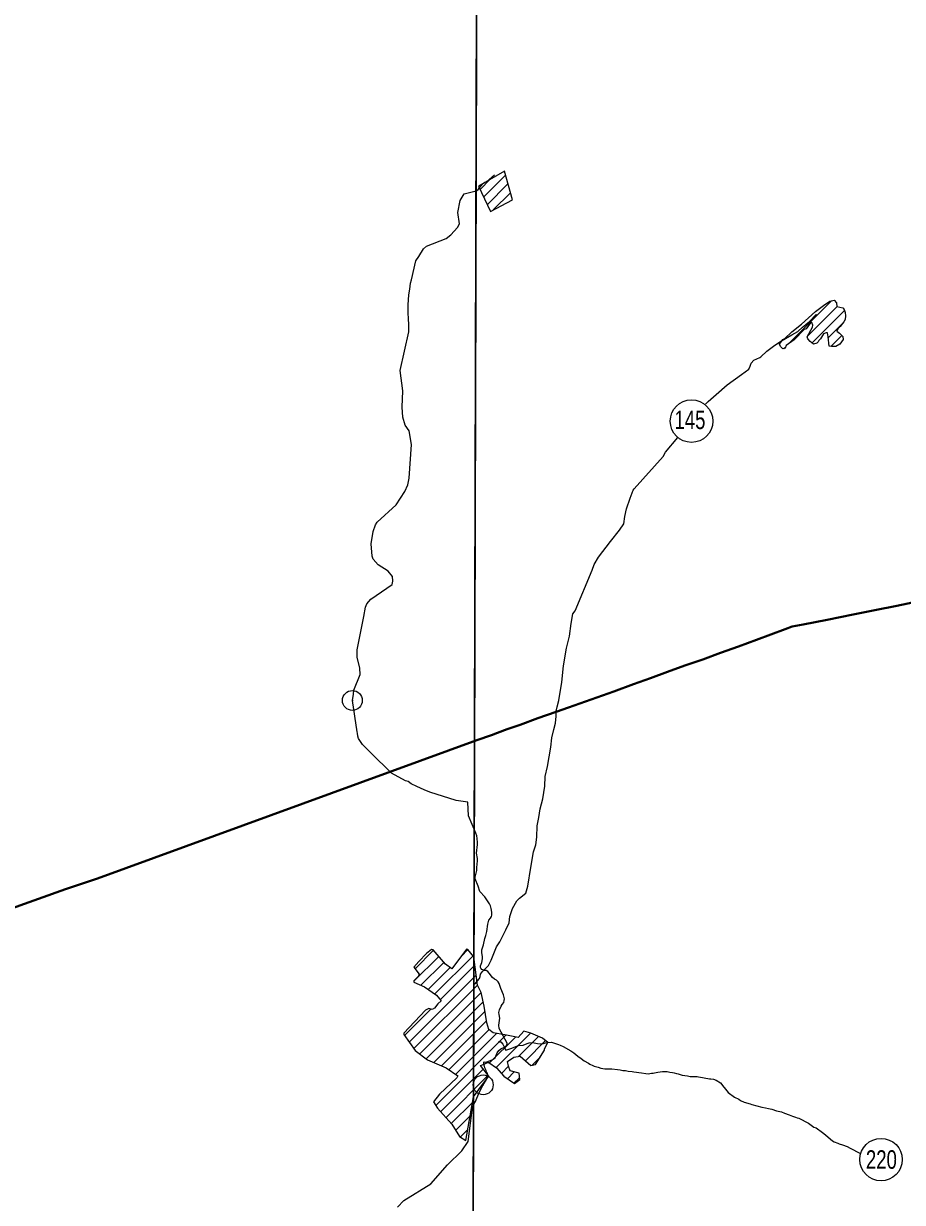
# Model space of a CAD drawing. Extents: x 553962 to 842807, y 8883888 to 9032388.
# Drawn here: x 583922 to 587242, y 8911869 to 8916321 of the extents above; entities that cross this region are included whole.
import ezdxf
from ezdxf.enums import TextEntityAlignment as Align

# ---------------------------------------------------------------- set-up
doc = ezdxf.new("R2010")
doc.units = 0
doc.header["$LTSCALE"] = 150
doc.header["$PDMODE"] = 32
doc.header["$PDSIZE"] = 75
doc.layers.add('6', color=7, linetype='Continuous', lineweight=13)

msp = doc.modelspace()

# ---------------------------------------------------------------- linework, layer by layer
at = {"layer": '6'}
for p, q in [((585646.2, 8915694.7), (585684.3, 8915732.9)), ((585659.8, 8915665.9), (585742.7, 8915748.8)), ((585654.5, 8915713.5), (585659, 8915718.1)), ((585673.4, 8915637.1), (585751.8, 8915715.5)), ((585696.2, 8915617.4), (585761, 8915682.2)), ((586813.8, 8915113.8), (586974.3, 8915274.2)), ((586882.8, 8915140.3), (586994.4, 8915251.9)), ((586900.1, 8915115.2), (587023, 8915238.1)), ((586961.6, 8915134.2), (587014.3, 8915187)), ((586972, 8915102.2), (587012.5, 8915142.8)), ((586794.2, 8915094.1), (586800.9, 8915100.8)), ((585164.2, 8913764.7), (585168, 8913788.9)), ((585396.8, 8912704.8), (585490.4, 8912798.3)), ((585400.9, 8912751.3), (585470.7, 8912821)), ((585475.4, 8912656.1), (585619.8, 8912800.4)), ((585574.5, 8912797.6), (585600.5, 8912823.6)), ((585423.2, 8912688.8), (585510.1, 8912775.6)), ((585450.2, 8912673.2), (585533, 8912756.1)), ((585495.7, 8912633.9), (585626.7, 8912764.9)), ((585378.8, 8912474.6), (585631.4, 8912727.2)), ((585396.4, 8912449.8), (585636.2, 8912689.5)), ((585418.5, 8912429.5), (585650.2, 8912661.2)), ((585442.6, 8912411.1), (585658.2, 8912626.7)), ((585361.2, 8912499.4), (585461.2, 8912599.4)), ((585471.2, 8912397.3), (585665.1, 8912591.2)), ((585501.1, 8912384.8), (585671, 8912554.7)), ((585528.9, 8912370.1), (585680.2, 8912521.4)), ((585478.8, 8912235.2), (585744.3, 8912500.7)), ((585553.8, 8912352.6), (585708.5, 8912507.3)), ((585682.1, 8912396.1), (585779.6, 8912493.6)), ((585706.9, 8912378.4), (585836.5, 8912508)), ((585791.3, 8912420.4), (585866.7, 8912495.8)), ((585817.4, 8912404.1), (585893.6, 8912480.2)), ((585726.9, 8912356), (585754.2, 8912383.3)), ((585842.2, 8912386.5), (585874.3, 8912418.5)), ((585497.3, 8912211.3), (585658.6, 8912372.5)), ((585517.3, 8912188.8), (585677.4, 8912349)), ((585749.5, 8912336.2), (585775.3, 8912362)), ((585774.5, 8912318.7), (585795.5, 8912339.8)), ((585537.3, 8912166.4), (585618.5, 8912247.6)), ((585554.2, 8912140.9), (585609.2, 8912195.9)), ((585572, 8912116.2), (585600, 8912144.3))]:
    msp.add_line(p, q, dxfattribs=at)
for points in [[(585656.3, 8924738.8), (585614.8, 8909969.8), (585573.6, 8896026.7)], [(585659.6, 8915718.8), (585664, 8915721.8), (585674.1, 8915726.3), (585679.1, 8915730.6), (585692.1, 8915742.6), (585701, 8915749.9)], [(585414.9, 8915441.5), (585432.8, 8915470.1), (585444.4, 8915480.8), (585518.2, 8915510), (585536, 8915523.2), (585560.6, 8915550.4), (585569.1, 8915565.3), (585561.9, 8915607.2), (585571.5, 8915653.5), (585585.9, 8915678), (585631.7, 8915689.4), (585634.6, 8915690.8), (585639.6, 8915694.9), (585655.2, 8915714.2)], [(585387.2, 8915353.3), (585404.3, 8915424.6), (585414.9, 8915441.5)], [(585376.5, 8915206.1), (585374.8, 8915228.7), (585374.3, 8915258.9), (585377.8, 8915297.1), (585380.9, 8915318.6), (585384.2, 8915340.2), (585387.2, 8915353.3)], [(585344.3, 8915010.4), (585377.6, 8915157), (585377.3, 8915185), (585376.5, 8915206.1)], [(585258.2, 8914437.7), (585330, 8914503.1), (585362.7, 8914553.7), (585373.3, 8914579.2), (585378.8, 8914604.6), (585387.7, 8914732), (585378.4, 8914783.1), (585363.1, 8914804.4), (585355, 8914834.1), (585351.6, 8914872.3), (585354.6, 8914933.5), (585344.3, 8915010.4)], [(585317.3, 8914216), (585316.1, 8914232.9), (585298.9, 8914252.4), (585262, 8914276.7), (585242.9, 8914298.7), (585238.3, 8914309.6), (585235.2, 8914355.7), (585242.8, 8914403.2), (585251.4, 8914427.6), (585258.2, 8914437.7)], [(585206.8, 8914082.2), (585213.6, 8914117), (585218.3, 8914129.3), (585233.9, 8914146.7), (585314.4, 8914203.2), (585317.3, 8914215.7), (585317.3, 8914216)], [(585168, 8913788.9), (585170.2, 8913803.4), (585194, 8913862.9), (585192.3, 8913886.6), (585182.1, 8913928.2), (585182.1, 8913956.3), (585206.8, 8914082.2)], [(585202.5, 8913598.6), (585187.4, 8913621.3), (585184.9, 8913630.1), (585183, 8913640.7), (585182.1, 8913645.8), (585164.2, 8913764.7)], [(585365.1, 8913461), (585312.1, 8913489.8), (585233.9, 8913567.4), (585202.5, 8913598.6)], [(585556.7, 8913386.5), (585456.6, 8913418.5), (585434.8, 8913426.6), (585408.2, 8913439.8), (585386, 8913450.3), (585374.6, 8913458.3), (585365.1, 8913461)], [(585630.2, 8913263.8), (585602.7, 8913329.2), (585600.5, 8913381), (585556.7, 8913386.5)], [(585736.2, 8912623.7), (585737.8, 8912631.2), (585738.3, 8912638), (585735.4, 8912652.4), (585724.9, 8912676.3), (585718.3, 8912696.1), (585715, 8912702.5), (585708.5, 8912708.9), (585700.5, 8912712.7), (585693.4, 8912718.1), (585681, 8912734.9), (585675.2, 8912740.7), (585669.2, 8912744.5), (585662.6, 8912744.7), (585653.1, 8912748.3), (585649.1, 8912753.1), (585647.6, 8912756.5), (585647.8, 8912762.3), (585652.8, 8912775.5), (585655.5, 8912788.5), (585655.4, 8912796.9), (585652.9, 8912813.2), (585653.4, 8912822.4), (585659.4, 8912841.6), (585663.8, 8912865.3), (585667.9, 8912876.9), (585671.8, 8912892.1), (585676, 8912920.4), (585680, 8912935.4), (585685.6, 8912942.4), (585689.2, 8912948.4), (585690.5, 8912953.8), (585690.6, 8912965.7), (585688.4, 8912978.7), (585685.4, 8912989.5), (585682.3, 8912996.3), (585663.9, 8913022.7), (585646, 8913043.7), (585639.3, 8913063.9), (585628.3, 8913091.6), (585627.9, 8913097.2), (585633.8, 8913122.4), (585634.1, 8913133.2), (585636.9, 8913159.3), (585636.4, 8913167.7), (585632.5, 8913187.7), (585636.7, 8913220.8), (585636.8, 8913228.4), (585635.7, 8913243), (585633.6, 8913253.8), (585630.2, 8913263.8)], [(585622.7, 8912796.8), (585600.5, 8912823.7), (585595.2, 8912825), (585539.5, 8912751.2), (585515.6, 8912769.3), (585469.4, 8912822.4), (585462.9, 8912823.7), (585443.5, 8912809), (585414.9, 8912778.3), (585415.6, 8912779)], [(585622.1, 8912267.7), (585652.2, 8912309.6), (585680.1, 8912345.6), (585648.2, 8912385.5), (585662.2, 8912391.5), (585674.1, 8912397.5), (585680.1, 8912397.5), (585708.1, 8912377.6), (585736.1, 8912345.6), (585776.1, 8912317.6), (585796.1, 8912333.6), (585794.1, 8912357.6), (585760.1, 8912365.6), (585754.1, 8912383.5), (585750.1, 8912401.5), (585774.1, 8912417.5), (585798.1, 8912421.5), (585838, 8912385.5), (585856, 8912389.5), (585890, 8912443.5), (585890, 8912449.5), (585902, 8912473.5), (585882, 8912489.5), (585838, 8912507.5), (585812.1, 8912515.5), (585790.1, 8912491.5), (585740.1, 8912501.5), (585696.1, 8912509.5), (585680.1, 8912521.5), (585672.1, 8912547.5), (585662.2, 8912609.5), (585650.2, 8912661.4), (585636.2, 8912689.4), (585622.7, 8912796.8)], [(585415.6, 8912779), (585396.2, 8912757.3), (585416.2, 8912731.2), (585414.5, 8912723), (585396.8, 8912705.3), (585396.8, 8912701), (585436.1, 8912682.8), (585481.6, 8912651.8), (585498.9, 8912629.7), (585486.4, 8912619.5), (585473.8, 8912602.6), (585466, 8912598.1), (585452.6, 8912601.9), (585439.9, 8912594.7), (585358.3, 8912507.7), (585358.3, 8912503.4), (585401.6, 8912442.4), (585447.4, 8912407.4), (585518.3, 8912377.6), (585561.9, 8912346.9), (585558.9, 8912339.9), (585492.8, 8912277.7), (585470.1, 8912248.8), (585485.7, 8912224.4), (585539.5, 8912164), (585568.8, 8912118.3), (585592.6, 8912103), (585622.1, 8912267.7)], [(585658.3, 8912313), (585669.3, 8912330.1), (585674.8, 8912344.1), (585674.7, 8912356.1), (585670, 8912363.9), (585669.5, 8912366.5), (585664.5, 8912377.1), (585660.4, 8912393.1), (585660.6, 8912399.1), (585661.4, 8912399.7), (585667, 8912398.8), (585671.5, 8912399.6), (585691.6, 8912407.8), (585703.4, 8912415.2), (585710.9, 8912433.7), (585717.4, 8912443.1), (585724.5, 8912449.1), (585741.6, 8912456.2), (585745.8, 8912461.4), (585749, 8912467.6), (585749.3, 8912469.8), (585718.8, 8912525.6), (585717.8, 8912538.1), (585721, 8912565.3), (585718.2, 8912578.9), (585717.9, 8912586.7), (585719.7, 8912596.1), (585725.9, 8912610.6), (585729.7, 8912616.2), (585736.2, 8912623.7)], [(585335.1, 8911850.8), (585358.8, 8911875.8), (585459.9, 8911939.1), (585523.3, 8912010.5), (585577.2, 8912063.6), (585601.4, 8912098.4), (585618, 8912226.8), (585623.8, 8912242.6), (585628.7, 8912250.5), (585642.8, 8912284.1), (585658.3, 8912313)]]:
    msp.add_lwpolyline(points, dxfattribs=at)
for points in [[(585645.8, 8921027.3), (574684.9, 8921064.7), (574653.9, 8910009.3), (585614.8, 8909969.8)], [(585640, 8915707.7), (585685.4, 8915611.8), (585768.3, 8915655.4), (585738.6, 8915763.7)], [(586913.1, 8915233.4), (586943.5, 8915256), (586968, 8915272.7), (586983.7, 8915276.6), (586992.5, 8915266.8), (586993.5, 8915252.1), (587016, 8915247.2), (587021.9, 8915241.3), (587025.8, 8915229.5), (587026.8, 8915216.8), (587024.8, 8915203), (587019.9, 8915194.2), (587006.2, 8915176.6), (586997.4, 8915168.7), (586993.5, 8915159.9), (587003.3, 8915152), (587016, 8915139.3), (587018, 8915127.5), (587005.2, 8915109.9), (586989.5, 8915102), (586973.9, 8915102), (586965, 8915103), (586961.1, 8915138.3), (586958.2, 8915153), (586953.3, 8915153), (586943.5, 8915149.1), (586931.7, 8915130.5), (586925.8, 8915124.6), (586922.9, 8915119.7), (586918, 8915113.8), (586906.2, 8915110.8), (586892.5, 8915120.7), (586884.6, 8915130.5), (586881.7, 8915138.3), (586901.3, 8915174.6), (586903.3, 8915182.4), (586899.3, 8915192.2), (586894.4, 8915190.3), (586877.8, 8915167.7), (586870.9, 8915165.8), (586832.7, 8915126.5), (586802.3, 8915105.9), (586799.3, 8915095.2), (586789.5, 8915093.2), (586780.7, 8915102), (586777.8, 8915110.8), (586790.5, 8915127.5), (586797.4, 8915131.4), (586823.8, 8915156.9), (586860.1, 8915186.4)]]:
    msp.add_lwpolyline(points, close=True, dxfattribs=at)
at = {"layer": '6', "lineweight": 25}
for points in [[(586706.4, 8915062.2), (586729.7, 8915084), (586760.1, 8915106.5), (586784.3, 8915123.2), (586823.6, 8915145.7), (586847, 8915158.3), (586863.6, 8915174), (586876.8, 8915185.2), (586890.9, 8915196.4), (586914.5, 8915221.7), (586915.6, 8915222.3), (586917.4, 8915222.5)], [(586497.7, 8914883.6), (586508.3, 8914893.6), (586538, 8914920.3), (586580.2, 8914956.6), (586633.3, 8914995.3), (586661.6, 8915016), (586666.2, 8915026.8), (586670.9, 8915039.1), (586680.2, 8915050.5), (586702.7, 8915060.1), (586706.4, 8915062.2)], [(586228.4, 8914563.8), (586338, 8914686.4), (586347.1, 8914702.6), (586393.3, 8914758.1)], [(586070, 8914257.2), (586077.1, 8914278.1), (586094.2, 8914305.4), (586139.4, 8914364.6), (586172.7, 8914407.5), (586190, 8914431.6), (586192.9, 8914459.2), (586200, 8914488.1), (586213.2, 8914528.1), (586224.4, 8914559.4), (586228.4, 8914563.8)], [(585934, 8913722), (585934.1, 8913727.4), (585935.2, 8913729.7), (585937.4, 8913740.1), (585943.5, 8913764.7), (585955.7, 8913833.7), (585961.6, 8913894.9), (585973, 8913962.3), (585983.6, 8914007.2), (585990.8, 8914055.1), (585996.9, 8914092.1), (586005.3, 8914103.8), (586070, 8914257.2)], [(585856.5, 8913219.1), (585860.7, 8913248.2), (585862.4, 8913291.7), (585868.5, 8913322.9), (585873.7, 8913355.2), (585882.9, 8913393), (585891, 8913440.9), (585892.9, 8913478), (585900.7, 8913515.9), (585913.7, 8913588.2), (585917.8, 8913623.5), (585925.6, 8913655.5), (585931.1, 8913678.4), (585934.2, 8913705.8), (585934, 8913722)], [(585623.2, 8912691.7), (585629.9, 8912698.6), (585644, 8912715.2), (585647.4, 8912722.6), (585647.8, 8912731), (585656, 8912741.3), (585677.9, 8912764.1), (585688.7, 8912784), (585708.8, 8912833.9), (585720.6, 8912852.9), (585744.2, 8912898.7), (585755.7, 8912925.3), (585758.6, 8912948.3), (585769, 8912979.4), (585785.3, 8913008.3), (585795.4, 8913017.5), (585819.2, 8913037.2), (585827, 8913063.2), (585838, 8913133.6), (585848.6, 8913192.5), (585856.5, 8913219.1)], [(585714.7, 8912475.9), (585724.1, 8912475.4), (585725.1, 8912474.8), (585731.8, 8912467), (585736.8, 8912456.3), (585742.8, 8912445.1), (585743.5, 8912444.3), (585763.1, 8912449.6), (585791.7, 8912461.8), (585809.2, 8912463.3), (585824.3, 8912469.3), (585831.6, 8912471.5), (585844.2, 8912472.3), (585850.6, 8912471.9), (585863.1, 8912469.2), (585875.1, 8912467.4), (585880.6, 8912467.8), (585886.4, 8912469), (585893.4, 8912471), (585899.8, 8912472.4), (585915.8, 8912474.7), (585942.4, 8912464.9), (585949, 8912463.1), (585959.9, 8912457.3), (585989.6, 8912441.1), (586000.1, 8912434.3), (586016.1, 8912421.7), (586027.8, 8912412.1), (586039.7, 8912403.8), (586056.1, 8912394.2), (586061.5, 8912391.2), (586072, 8912386.2), (586077.3, 8912384), (586087, 8912380.8), (586092.6, 8912379.8), (586102.9, 8912376.2), (586118.2, 8912374), (586137.9, 8912373.1), (586144, 8912373.1), (586164.9, 8912371.5), (586175.2, 8912369.5), (586180.3, 8912368.1), (586185.2, 8912367.3), (586190.5, 8912366.9), (586195.8, 8912366.7), (586205.8, 8912365.2), (586221, 8912363.6), (586226.7, 8912362.2), (586256.6, 8912358.6), (586272.5, 8912355.8), (586282.2, 8912354.8), (586287.7, 8912355.5), (586293.6, 8912356.7), (586300, 8912357.1), (586305.6, 8912358.1), (586317.3, 8912360.9), (586335.4, 8912362.9), (586335.4, 8912362.9), (586348, 8912363.6)], [(586348, 8912363.6), (586353.5, 8912363), (586363.2, 8912361.4), (586373.8, 8912359), (586379.8, 8912358.2), (586388.9, 8912356), (586394.6, 8912354), (586409.6, 8912349.8), (586430, 8912346.7), (586435.1, 8912345.5), (586439.7, 8912344.7), (586450.3, 8912344.3), (586456.2, 8912344.7), (586466.5, 8912344.1), (586471.8, 8912342.9), (586486.8, 8912340.8), (586492.6, 8912339.4), (586512.4, 8912336), (586518, 8912335.8), (586528.4, 8912334.6), (586538.3, 8912330.6), (586554.6, 8912320.6), (586566.6, 8912304.4), (586568.3, 8912303), (586577.9, 8912290.2), (586583.1, 8912284.6), (586607.6, 8912267), (586623.2, 8912258.4), (586629.7, 8912253.2), (586643.5, 8912247.5), (586666.8, 8912241.5), (586673.2, 8912239.3), (586710.9, 8912228.5), (586724.5, 8912226.6), (586736.3, 8912223.8), (586742.6, 8912222.6), (586748.4, 8912221), (586766.5, 8912215), (586784.4, 8912210.6), (586796.5, 8912206.4), (586814.4, 8912199.1), (586826, 8912195.1), (586837.7, 8912191.3), (586843.9, 8912188.7), (586850.1, 8912186.7), (586886.9, 8912168.1), (586907.5, 8912153.5), (586915.4, 8912150.1), (586939.5, 8912132.9), (586950.7, 8912123.9), (586970.1, 8912107.2), (586976.9, 8912102), (586984.3, 8912097.8), (586997.1, 8912092.2), (587002.8, 8912090.2), (587014.6, 8912085.8), (587032.8, 8912080.2), (587044.3, 8912074.2), (587056.4, 8912067.2), (587068.5, 8912060.6), (587083.5, 8912053.1)]]:
    msp.add_lwpolyline(points, dxfattribs=at)
at = {"layer": '6', "lineweight": 40}
for points in [[(587942.9, 8914269.9), (587894.7, 8914259.8), (587797.8, 8914239.6), (587700.8, 8914220), (587586.4, 8914197.2), (587471.4, 8914174.2), (587387.3, 8914155.4), (587304, 8914139.1), (587220.7, 8914122.7), (587137.7, 8914106.3), (587056.1, 8914089), (587006.5, 8914079.3)], [(587006.5, 8914079.3), (586956.9, 8914069.8), (586911.4, 8914060.1), (586866.7, 8914051.8), (586825.2, 8914043.6), (586798.3, 8914033.5), (586690.9, 8913993.9), (586622.7, 8913968.9), (586555, 8913944.4), (586487.3, 8913919.8), (586419.9, 8913896.5), (586354.1, 8913872.9), (586290, 8913849.2), (586225.8, 8913825.7), (586151.9, 8913798.9), (586066.1, 8913768.3), (585980.4, 8913738.3), (585934, 8913722)], [(585934, 8913722), (585864.5, 8913697.7), (585798.1, 8913673.2), (585748.7, 8913656.8), (585711.9, 8913642.6), (585690.2, 8913634.1), (585634.1, 8913614.2)], [(583859, 8912972.9), (584080.2, 8913052.4), (584201.3, 8913092.2), (585634.1, 8913614.2)]]:
    msp.add_lwpolyline(points, dxfattribs=at)
at = {"layer": '6', "lineweight": 25}
for centre in [(586445.1, 8914819.6), (587160.8, 8912030.6)]:
    msp.add_circle(centre, 80.3, dxfattribs=at)
at = {"layer": '6'}
for p in [(585164.2, 8913764.7), (585658.3, 8912313)]:
    msp.add_point(p, dxfattribs=at)

# ---------------------------------------------------------------- texts
at = {"layer": '6', "width": 0.75}
for s, p in [('145', (586439, 8914789.8)), ('220', (587162.1, 8911995.9))]:
    msp.add_text(s, height=70, dxfattribs=at).set_placement(p, align=Align.CENTER)

doc.saveas('drawing.dxf')
